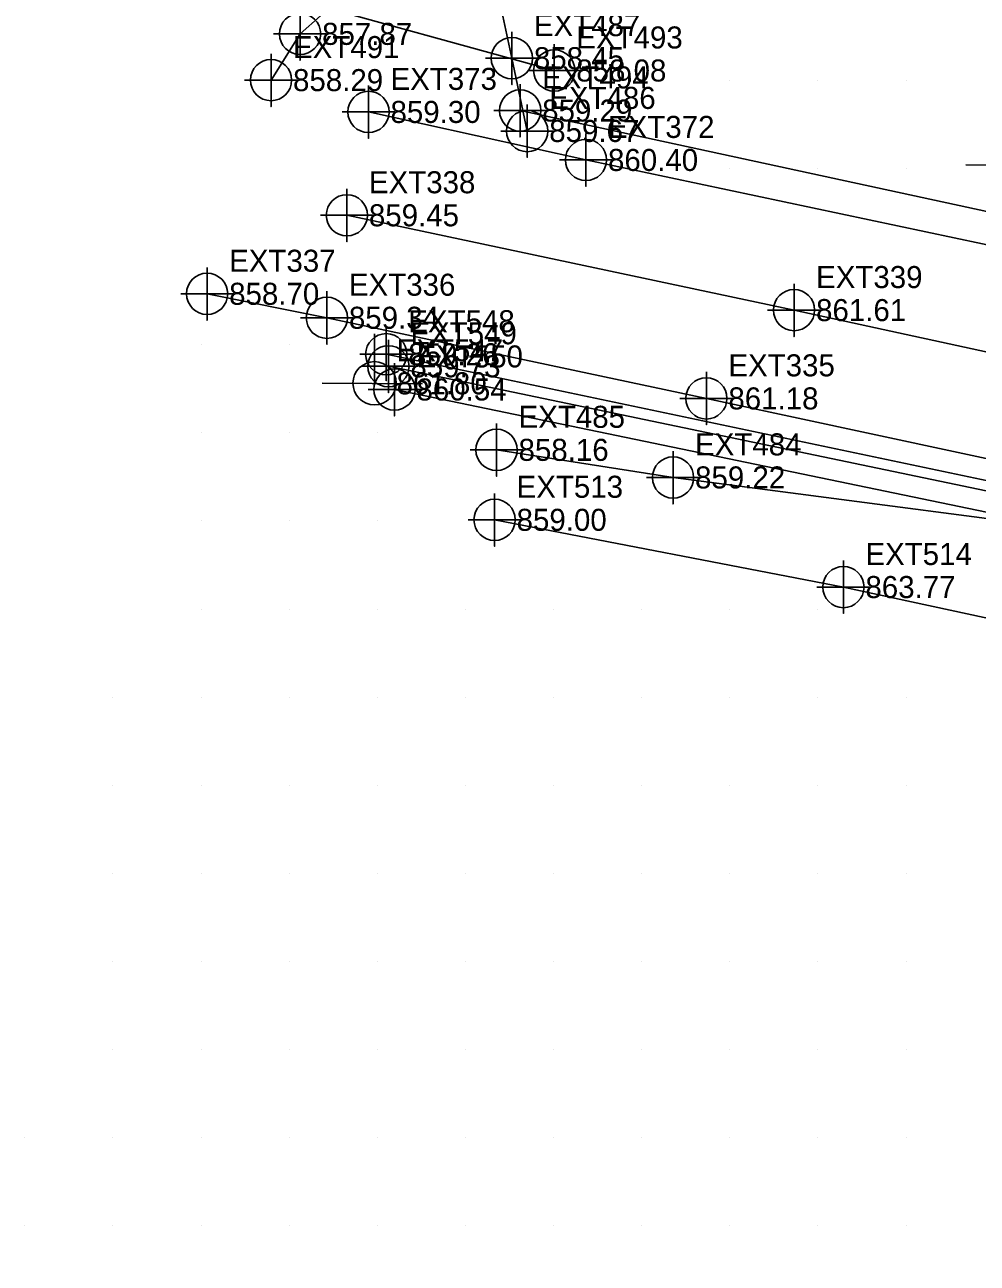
# Model space of a CAD drawing. Extents: x 1762120 to 1766775, y 709485 to 712965.
# Drawn here: x 1762130 to 1762238.1, y 712655.8 to 712796.3 of the extents above; entities that cross this region are included whole.
import ezdxf

# ---------------------------------------------------------------- set-up
doc = ezdxf.new("R2010")
doc.units = 0
for name, color, linetype in [('Exist DTM Breakline', 7, 'Continuous'), ('Exist DTM Breakline Cogo Elevation', 7, 'Continuous'), ('Exist DTM Breakline Cogo Number', 7, 'Continuous'), ('Exist DTM Breakline Cogo Point CELL', 7, 'Continuous'), ('Exist DTM Crownline', 7, 'Continuous'), ('Exist DTM Crownline Cogo Elevation', 7, 'Continuous'), ('Exist DTM Crownline Cogo Number', 7, 'Continuous'), ('Exist DTM Crownline Cogo Point CELL', 7, 'Continuous'), ('Exist DTM Drainline', 7, 'Continuous'), ('Exist DTM Drainline Cogo Elevation', 7, 'Continuous'), ('Exist DTM Drainline Cogo Number', 7, 'Continuous'), ('Exist DTM Drainline Cogo Point CELL', 7, 'Continuous'), ('Exist DTM QL2 LIDAR Elevation Point', 7, 'Continuous'), ('Exist Roads EOP', 7, 'Continuous'), ('Exist Roads EOP Cogo Elevation', 7, 'Continuous'), ('Exist Roads EOP Cogo Number', 7, 'Continuous'), ('Exist Roads EOP Cogo Point CELL', 7, 'Continuous'), ('Exist Roads EOP Other', 7, 'Continuous'), ('Exist Roads EOP Other Cogo Elevation', 7, 'Continuous'), ('Exist Roads EOP Other Cogo Number', 7, 'Continuous'), ('Exist Roads EOP Other Cogo Point CELL', 7, 'Continuous'), ('Exist Structure Minor Pipes RCP 15 Inch', 7, 'Continuous'), ('Exist Structure Minor Pipes RCP 15 Inch Cogo Elevation', 7, 'Continuous'), ('Exist Structure Minor Pipes RCP 15 Inch Cogo Number', 7, 'Continuous'), ('Exist Structure Minor Pipes RCP 15 Inch Cogo Point CELL', 7, 'Continuous'), ('Exist Utilities Gas UG Line SUE LOS C', 7, 'Continuous'), ('Exist Utilities Gas UG Line SUE LOS C Cogo Elevation', 7, 'Continuous'), ('Exist Utilities Gas UG Line SUE LOS C Cogo Number', 7, 'Continuous'), ('Exist Utilities Gas UG Line SUE LOS C Cogo Point CELL', 7, 'Continuous'), ('Exist Utilities Power Joint Use Telephone CELL', 7, 'Continuous'), ('Exist Utilities Power Joint Use Telephone Cogo Elevation', 7, 'Continuous'), ('Exist Utilities Power Joint Use Telephone Cogo Number', 7, 'Continuous'), ('Exist Utilities Telephone UG FO SUE LOS C', 7, 'Continuous'), ('Exist Utilities Telephone UG FO SUE LOS C Cogo Elevation', 7, 'Continuous'), ('Exist Utilities Telephone UG FO SUE LOS C Cogo Number', 7, 'Continuous'), ('Exist Utilities Telephone UG FO SUE LOS C Cogo Point CELL', 7, 'Continuous'), ('Exist Utilities Water UG Line SUE LOS C', 7, 'Continuous'), ('Exist Utilities Water UG Line SUE LOS C Cogo Elevation', 7, 'Continuous'), ('Exist Utilities Water UG Line SUE LOS C Cogo Number', 7, 'Continuous'), ('Exist Utilities Water UG Line SUE LOS C Cogo Point CELL', 7, 'Continuous')]:
    doc.layers.add(name, color=color, linetype=linetype)

msp = doc.modelspace()

# ---------------------------------------------------------------- linework, layer by layer
at = {"layer": 'Exist DTM Breakline'}
msp.add_lwpolyline([(1762183.31, 712740.13), (1762222.89, 712732.5), (1762242.72, 712728.2), (1762260.87, 712722.96), (1762294.89, 712713.63), (1762324.74, 712704.89), (1762362.52, 712694.51), (1762387.62, 712687.36), (1762406.26, 712681.83), (1762438.55, 712677.19), (1762458.9, 712672.51), (1762474.39, 712669.93), (1762496.2, 712663.55), (1762513.05, 712661.01), (1762547.19, 712657.24), (1762571.69, 712653.16), (1762593.37, 712650.89), (1762601.1, 712652.92), (1762602.91, 712656.27)], dxfattribs=at)
at = {"layer": 'Exist DTM Breakline Cogo Point CELL'}
for points in [[(1762183.31, 712743.13), (1762183.31, 712737.13), (1762183.31, 712740.13), (1762186.31, 712740.13), (1762180.31, 712740.13)], [(1762222.89, 712735.5), (1762222.89, 712729.5), (1762222.89, 712732.5), (1762225.89, 712732.5), (1762219.89, 712732.5)]]:
    msp.add_lwpolyline(points, dxfattribs=at)
for centre in [(1762183.31, 712740.13), (1762222.89, 712732.5)]:
    msp.add_circle(centre, 2.34, dxfattribs=at)
at = {"layer": 'Exist DTM Crownline'}
msp.add_lwpolyline([(1762166.55, 712774.69), (1762217.29, 712763.93), (1762266.93, 712753.16), (1762315.99, 712742.65), (1762361.3, 712733.13), (1762409.52, 712722.71), (1762461.51, 712711.51), (1762512.12, 712700.31), (1762561, 712689.86), (1762611.48, 712678.84), (1762663.77, 712667.96), (1762715.27, 712656.97), (1762767.73, 712645.75), (1762820.16, 712634.42), (1762873.56, 712623.12), (1762907.32, 712615.87), (1762954.84, 712607.61), (1762970.66, 712604.72)], dxfattribs=at)
at = {"layer": 'Exist DTM Crownline Cogo Point CELL'}
for points in [[(1762166.55, 712777.69), (1762166.55, 712771.69), (1762166.55, 712774.69), (1762169.55, 712774.69), (1762163.55, 712774.69)], [(1762217.29, 712766.93), (1762217.29, 712760.93), (1762217.29, 712763.93), (1762220.29, 712763.93), (1762214.29, 712763.93)]]:
    msp.add_lwpolyline(points, dxfattribs=at)
for centre in [(1762166.55, 712774.69), (1762217.29, 712763.93)]:
    msp.add_circle(centre, 2.34, dxfattribs=at)
at = {"layer": 'Exist DTM Drainline'}
msp.add_lwpolyline([(1762607.34, 712658.7), (1762593.44, 712665.01), (1762568.56, 712671.1), (1762531.51, 712678.41), (1762506.12, 712683.06), (1762483.93, 712688.33), (1762453.21, 712695.91), (1762419.5, 712702.24), (1762383.47, 712709.67), (1762355.69, 712715.12), (1762331.82, 712720.47), (1762302.4, 712727.8), (1762276.98, 712733.51), (1762241.78, 712739.93), (1762203.56, 712744.93), (1762183.53, 712748.07)], dxfattribs=at)
at = {"layer": 'Exist DTM Drainline Cogo Point CELL'}
for points in [[(1762183.53, 712751.07), (1762183.53, 712745.07), (1762183.53, 712748.07), (1762186.53, 712748.07), (1762180.53, 712748.07)], [(1762203.56, 712747.93), (1762203.56, 712741.93), (1762203.56, 712744.93), (1762206.56, 712744.93), (1762200.56, 712744.93)]]:
    msp.add_lwpolyline(points, dxfattribs=at)
for centre in [(1762183.53, 712748.07), (1762203.56, 712744.93)]:
    msp.add_circle(centre, 2.34, dxfattribs=at)
at = {"layer": 'Exist DTM QL2 LIDAR Elevation Point'}
for p, q in [((1762190, 712790), (1762190, 712790)), ((1762200, 712790), (1762200, 712790)), ((1762210, 712790), (1762210, 712790)), ((1762220, 712790), (1762220, 712790)), ((1762230, 712790), (1762230, 712790)), ((1762210, 712780), (1762210, 712780)), ((1762220, 712780), (1762220, 712780)), ((1762230, 712780), (1762230, 712780)), ((1762150, 712760), (1762150, 712760)), ((1762160, 712760), (1762160, 712760)), ((1762150, 712750), (1762150, 712750)), ((1762160, 712750), (1762160, 712750)), ((1762170, 712750), (1762170, 712750)), ((1762150, 712740), (1762150, 712740)), ((1762160, 712740), (1762160, 712740)), ((1762170, 712740), (1762170, 712740)), ((1762150, 712730), (1762150, 712730)), ((1762160, 712730), (1762160, 712730)), ((1762170, 712730), (1762170, 712730)), ((1762180, 712730), (1762180, 712730)), ((1762190, 712730), (1762190, 712730)), ((1762200, 712730), (1762200, 712730)), ((1762210, 712730), (1762210, 712730)), ((1762220, 712730), (1762220, 712730)), ((1762140, 712720), (1762140, 712720)), ((1762150, 712720), (1762150, 712720)), ((1762160, 712720), (1762160, 712720)), ((1762170, 712720), (1762170, 712720)), ((1762180, 712720), (1762180, 712720)), ((1762190, 712720), (1762190, 712720)), ((1762200, 712720), (1762200, 712720)), ((1762210, 712720), (1762210, 712720)), ((1762220, 712720), (1762220, 712720)), ((1762230, 712720), (1762230, 712720)), ((1762140, 712710), (1762140, 712710)), ((1762150, 712710), (1762150, 712710)), ((1762160, 712710), (1762160, 712710)), ((1762170, 712710), (1762170, 712710)), ((1762180, 712710), (1762180, 712710)), ((1762190, 712710), (1762190, 712710)), ((1762200, 712710), (1762200, 712710)), ((1762210, 712710), (1762210, 712710)), ((1762220, 712710), (1762220, 712710)), ((1762230, 712710), (1762230, 712710)), ((1762140, 712700), (1762140, 712700)), ((1762150, 712700), (1762150, 712700)), ((1762160, 712700), (1762160, 712700)), ((1762170, 712700), (1762170, 712700)), ((1762180, 712700), (1762180, 712700)), ((1762190, 712700), (1762190, 712700)), ((1762200, 712700), (1762200, 712700)), ((1762210, 712700), (1762210, 712700)), ((1762220, 712700), (1762220, 712700)), ((1762230, 712700), (1762230, 712700)), ((1762140, 712690), (1762140, 712690)), ((1762150, 712690), (1762150, 712690)), ((1762160, 712690), (1762160, 712690)), ((1762170, 712690), (1762170, 712690)), ((1762180, 712690), (1762180, 712690)), ((1762190, 712690), (1762190, 712690)), ((1762200, 712690), (1762200, 712690)), ((1762210, 712690), (1762210, 712690)), ((1762220, 712690), (1762220, 712690)), ((1762230, 712690), (1762230, 712690)), ((1762140, 712680), (1762140, 712680)), ((1762150, 712680), (1762150, 712680)), ((1762160, 712680), (1762160, 712680)), ((1762170, 712680), (1762170, 712680)), ((1762180, 712680), (1762180, 712680)), ((1762190, 712680), (1762190, 712680)), ((1762200, 712680), (1762200, 712680)), ((1762210, 712680), (1762210, 712680)), ((1762220, 712680), (1762220, 712680)), ((1762230, 712680), (1762230, 712680)), ((1762130, 712670), (1762130, 712670)), ((1762140, 712670), (1762140, 712670)), ((1762150, 712670), (1762150, 712670)), ((1762160, 712670), (1762160, 712670)), ((1762170, 712670), (1762170, 712670)), ((1762180, 712670), (1762180, 712670)), ((1762190, 712670), (1762190, 712670)), ((1762200, 712670), (1762200, 712670)), ((1762210, 712670), (1762210, 712670)), ((1762220, 712670), (1762220, 712670)), ((1762230, 712670), (1762230, 712670)), ((1762130, 712660), (1762130, 712660)), ((1762140, 712660), (1762140, 712660)), ((1762150, 712660), (1762150, 712660)), ((1762160, 712660), (1762160, 712660)), ((1762170, 712660), (1762170, 712660)), ((1762180, 712660), (1762180, 712660)), ((1762190, 712660), (1762190, 712660)), ((1762200, 712660), (1762200, 712660)), ((1762210, 712660), (1762210, 712660)), ((1762220, 712660), (1762220, 712660)), ((1762230, 712660), (1762230, 712660))]:
    msp.add_line(p, q, dxfattribs=at)
at = {"layer": 'Exist Roads EOP'}
for points in [[(1762972.64, 712616.33), (1762930.48, 712622.91), (1762881.99, 712633.2), (1762831.97, 712644.06), (1762782.82, 712654.41), (1762735.74, 712664.41), (1762686.68, 712675.53), (1762639.56, 712685.27), (1762589.4, 712696.15), (1762546.23, 712705.49), (1762496.4, 712716.08), (1762446.15, 712726.9), (1762396.23, 712737.69), (1762346.43, 712748.23), (1762295.97, 712759.18), (1762245.1, 712770.1), (1762193.68, 712780.97), (1762169, 712786.42)], [(1762974.58, 712585.31), (1762927.98, 712597.84), (1762890.67, 712606.3), (1762842.51, 712617.09), (1762793.23, 712628.15), (1762744.7, 712638.79), (1762696.33, 712649.07), (1762645.67, 712659.58), (1762597.31, 712669.97), (1762548.88, 712680.54), (1762499.87, 712691.04), (1762451.78, 712701.31), (1762402.08, 712712.16), (1762353.64, 712722.59), (1762304.8, 712733.11), (1762255.13, 712743.65), (1762207.34, 712753.91), (1762164.28, 712763.06), (1762150.69, 712765.78)]]:
    msp.add_lwpolyline(points, dxfattribs=at)
at = {"layer": 'Exist Roads EOP Cogo Point CELL'}
for points in [[(1762169, 712789.42), (1762169, 712783.42), (1762169, 712786.42), (1762172, 712786.42), (1762166, 712786.42)], [(1762193.68, 712783.97), (1762193.68, 712777.97), (1762193.68, 712780.97), (1762196.68, 712780.97), (1762190.68, 712780.97)], [(1762150.69, 712768.78), (1762150.69, 712762.78), (1762150.69, 712765.78), (1762153.69, 712765.78), (1762147.69, 712765.78)], [(1762164.28, 712766.06), (1762164.28, 712760.06), (1762164.28, 712763.06), (1762167.28, 712763.06), (1762161.28, 712763.06)], [(1762207.34, 712756.91), (1762207.34, 712750.91), (1762207.34, 712753.91), (1762210.34, 712753.91), (1762204.34, 712753.91)]]:
    msp.add_lwpolyline(points, dxfattribs=at)
for centre in [(1762169, 712786.42), (1762193.68, 712780.97), (1762150.69, 712765.78), (1762164.28, 712763.06), (1762207.34, 712753.91)]:
    msp.add_circle(centre, 2.34, dxfattribs=at)
at = {"layer": 'Exist Roads EOP Other'}
for points in [[(1762170.48, 712803.49), (1762161.24, 712795.28), (1762157.94, 712790.03)], [(1762187.01, 712784.25), (1762185.27, 712792.52), (1762183.69, 712799.99)]]:
    msp.add_lwpolyline(points, dxfattribs=at)
at = {"layer": 'Exist Roads EOP Other Cogo Point CELL'}
for points in [[(1762161.24, 712798.28), (1762161.24, 712792.28), (1762161.24, 712795.28), (1762164.24, 712795.28), (1762158.24, 712795.28)], [(1762185.27, 712795.52), (1762185.27, 712789.52), (1762185.27, 712792.52), (1762188.27, 712792.52), (1762182.27, 712792.52)], [(1762157.94, 712793.03), (1762157.94, 712787.03), (1762157.94, 712790.03), (1762160.94, 712790.03), (1762154.94, 712790.03)], [(1762187.01, 712787.25), (1762187.01, 712781.25), (1762187.01, 712784.25), (1762190.01, 712784.25), (1762184.01, 712784.25)]]:
    msp.add_lwpolyline(points, dxfattribs=at)
for centre in [(1762161.24, 712795.28), (1762185.27, 712792.52), (1762157.94, 712790.03), (1762187.01, 712784.25)]:
    msp.add_circle(centre, 2.34, dxfattribs=at)
at = {"layer": 'Exist Structure Minor Pipes RCP 15 Inch'}
msp.add_line((1762159.86, 712799.47), (1762190.08, 712791.12), dxfattribs=at)
at = {"layer": 'Exist Structure Minor Pipes RCP 15 Inch Cogo Point CELL'}
msp.add_lwpolyline([(1762190.08, 712794.12), (1762190.08, 712788.12), (1762190.08, 712791.12), (1762193.08, 712791.12), (1762187.08, 712791.12)], dxfattribs=at)
msp.add_circle((1762190.08, 712791.12), 2.34, dxfattribs=at)
at = {"layer": 'Exist Utilities Gas UG Line SUE LOS C'}
msp.add_lwpolyline([(1762186.21, 712786.58), (1762241.95, 712774.53), (1762368.98, 712745.66), (1762446.66, 712730.32), (1762499.18, 712718.67), (1762560.33, 712705.06), (1762614.27, 712693.34), (1762654.57, 712685.66), (1762695.77, 712676.76), (1762747.57, 712665.85), (1762826.12, 712649.31), (1762887.98, 712636.74)], dxfattribs=at)
at = {"layer": 'Exist Utilities Gas UG Line SUE LOS C Cogo Point CELL'}
msp.add_lwpolyline([(1762186.21, 712789.58), (1762186.21, 712783.58), (1762186.21, 712786.58), (1762189.21, 712786.58), (1762183.21, 712786.58)], dxfattribs=at)
msp.add_circle((1762186.21, 712786.58), 2.34, dxfattribs=at)
at = {"layer": 'Exist Utilities Power Joint Use Telephone CELL'}
msp.add_line((1762169.69, 712755.62), (1762169.69, 712755.62), dxfattribs=at)
for points in [[(1762236.77, 712780.43), (1762248.1, 712780.39), (1762242.71, 712780.41), (1762242.71, 712786.05)], [(1762163.75, 712755.62), (1762175.09, 712755.58), (1762169.69, 712755.6), (1762169.69, 712761.24)]]:
    msp.add_lwpolyline(points, dxfattribs=at)
msp.add_circle((1762169.69, 712755.63), 2.45, dxfattribs=at)
at = {"layer": 'Exist Utilities Telephone UG FO SUE LOS C'}
for points in [[(1762655.15, 712653.25), (1762586.52, 712669.54), (1762459.67, 712695.94), (1762295.49, 712731.66), (1762171.26, 712757.55)], [(1762655.08, 712650.85), (1762586.39, 712667.09), (1762459.96, 712694.03), (1762295.89, 712729.25), (1762171.95, 712754.92)]]:
    msp.add_lwpolyline(points, dxfattribs=at)
at = {"layer": 'Exist Utilities Telephone UG FO SUE LOS C Cogo Point CELL'}
for points in [[(1762171.26, 712760.55), (1762171.26, 712754.55), (1762171.26, 712757.55), (1762174.26, 712757.55), (1762168.26, 712757.55)], [(1762171.95, 712757.92), (1762171.95, 712751.92), (1762171.95, 712754.92), (1762174.95, 712754.92), (1762168.95, 712754.92)]]:
    msp.add_lwpolyline(points, dxfattribs=at)
for centre in [(1762171.26, 712757.55), (1762171.95, 712754.92)]:
    msp.add_circle(centre, 2.34, dxfattribs=at)
at = {"layer": 'Exist Utilities Water UG Line SUE LOS C'}
msp.add_lwpolyline([(1762652.6, 712655.88), (1762584.51, 712671.06), (1762460.33, 712696.95), (1762295.33, 712732.74), (1762171.02, 712758.92)], dxfattribs=at)
at = {"layer": 'Exist Utilities Water UG Line SUE LOS C Cogo Point CELL'}
msp.add_lwpolyline([(1762171.02, 712761.92), (1762171.02, 712755.92), (1762171.02, 712758.92), (1762174.02, 712758.92), (1762168.02, 712758.92)], dxfattribs=at)
msp.add_circle((1762171.02, 712758.92), 2.34, dxfattribs=at)

# ---------------------------------------------------------------- texts
at = {"layer": 'Exist DTM Breakline Cogo Elevation'}
for s, p in [('859.00', (1762185.81, 712738.88)), ('863.77', (1762225.39, 712731.25))]:
    msp.add_text(s, height=2.5, dxfattribs=at).set_placement(p)
at = {"layer": 'Exist DTM Breakline Cogo Number'}
for s, p in [('EXT513', (1762185.81, 712742.63)), ('EXT514', (1762225.39, 712735))]:
    msp.add_text(s, height=2.5, dxfattribs=at).set_placement(p)
at = {"layer": 'Exist DTM Crownline Cogo Elevation'}
for s, p in [('859.45', (1762169.05, 712773.44)), ('861.61', (1762219.79, 712762.68))]:
    msp.add_text(s, height=2.5, dxfattribs=at).set_placement(p)
at = {"layer": 'Exist DTM Crownline Cogo Number'}
for s, p in [('EXT338', (1762169.05, 712777.19)), ('EXT339', (1762219.79, 712766.43))]:
    msp.add_text(s, height=2.5, dxfattribs=at).set_placement(p)
at = {"layer": 'Exist DTM Drainline Cogo Elevation'}
for s, p in [('858.16', (1762186.03, 712746.82)), ('859.22', (1762206.06, 712743.69))]:
    msp.add_text(s, height=2.5, dxfattribs=at).set_placement(p)
at = {"layer": 'Exist DTM Drainline Cogo Number'}
for s, p in [('EXT485', (1762186.03, 712750.57)), ('EXT484', (1762206.06, 712747.44))]:
    msp.add_text(s, height=2.5, dxfattribs=at).set_placement(p)
at = {"layer": 'Exist Roads EOP Cogo Elevation'}
for s, p in [('859.30', (1762171.5, 712785.17)), ('860.40', (1762196.18, 712779.72)), ('858.70', (1762153.19, 712764.53)), ('859.34', (1762166.78, 712761.81)), ('861.18', (1762209.84, 712752.66))]:
    msp.add_text(s, height=2.5, dxfattribs=at).set_placement(p)
at = {"layer": 'Exist Roads EOP Cogo Number'}
for s, p in [('EXT373', (1762171.5, 712788.92)), ('EXT372', (1762196.18, 712783.47)), ('EXT337', (1762153.19, 712768.28)), ('EXT336', (1762166.78, 712765.56)), ('EXT335', (1762209.84, 712756.41))]:
    msp.add_text(s, height=2.5, dxfattribs=at).set_placement(p)
at = {"layer": 'Exist Roads EOP Other Cogo Elevation'}
for s, p in [('857.87', (1762163.74, 712794.03)), ('858.45', (1762187.77, 712791.27)), ('858.29', (1762160.44, 712788.78)), ('859.67', (1762189.51, 712783.01))]:
    msp.add_text(s, height=2.5, dxfattribs=at).set_placement(p)
at = {"layer": 'Exist Roads EOP Other Cogo Number'}
for s, p in [('EXT487', (1762187.77, 712795.02)), ('EXT491', (1762160.44, 712792.53)), ('EXT486', (1762189.51, 712786.76))]:
    msp.add_text(s, height=2.5, dxfattribs=at).set_placement(p)
at = {"layer": 'Exist Structure Minor Pipes RCP 15 Inch Cogo Elevation'}
msp.add_text('858.08', height=2.5, dxfattribs=at).set_placement((1762192.58, 712789.87))
at = {"layer": 'Exist Structure Minor Pipes RCP 15 Inch Cogo Number'}
msp.add_text('EXT493', height=2.5, dxfattribs=at).set_placement((1762192.58, 712793.62))
at = {"layer": 'Exist Utilities Gas UG Line SUE LOS C Cogo Elevation'}
msp.add_text('859.29', height=2.5, dxfattribs=at).set_placement((1762188.71, 712785.33))
at = {"layer": 'Exist Utilities Gas UG Line SUE LOS C Cogo Number'}
msp.add_text('EXT494', height=2.5, dxfattribs=at).set_placement((1762188.71, 712789.08))
at = {"layer": 'Exist Utilities Power Joint Use Telephone Cogo Elevation'}
msp.add_text('861.80', height=2.5, dxfattribs=at).set_placement((1762172.19, 712754.37))
at = {"layer": 'Exist Utilities Power Joint Use Telephone Cogo Number'}
msp.add_text('EXT547', height=2.5, dxfattribs=at).set_placement((1762172.19, 712758.12))
at = {"layer": 'Exist Utilities Telephone UG FO SUE LOS C Cogo Elevation'}
for s, p in [('859.73', (1762173.76, 712756.3)), ('860.54', (1762174.45, 712753.67))]:
    msp.add_text(s, height=2.5, dxfattribs=at).set_placement(p)
at = {"layer": 'Exist Utilities Telephone UG FO SUE LOS C Cogo Number'}
for s, p in [('EXT549', (1762173.76, 712760.05)), ('EXT550', (1762174.45, 712757.42))]:
    msp.add_text(s, height=2.5, dxfattribs=at).set_placement(p)
at = {"layer": 'Exist Utilities Water UG Line SUE LOS C Cogo Elevation'}
msp.add_text('859.26', height=2.5, dxfattribs=at).set_placement((1762173.52, 712757.67))
at = {"layer": 'Exist Utilities Water UG Line SUE LOS C Cogo Number'}
msp.add_text('EXT548', height=2.5, dxfattribs=at).set_placement((1762173.52, 712761.42))

doc.saveas('drawing.dxf')
